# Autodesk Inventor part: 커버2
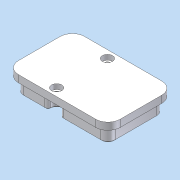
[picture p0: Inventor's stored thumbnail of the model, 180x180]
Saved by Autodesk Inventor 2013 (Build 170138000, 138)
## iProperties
Company: 한국ATC센터
Created: 2015-04
Part Number: 커버2
Document SubType Name: Modeling
Designer: KYOUNG IL JANG
Density: 1 g/cm^3
Material: 알루미늄 6061
Mass: 82.2849 g
Surface Area: 213.51 cm^2
Volume: 82.2849 cm^3
Author: KYOUNG IL JANG
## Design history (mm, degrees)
node "작업 평면1"
sketch "스케치1"
  geometry: L1 (-16.986, 27.5)-(-38, 27.5) reference; L2 (-45, 20.5)-(-45, -20.5) reference; L3 (-38, -27.5)-(-16.986, -27.5) reference; L4 (0.986, -27.5)-(38, -27.5) reference; L5 (45, -20.5)-(45, 20.5) reference; L6 (38, 27.5)-(0.986, 27.5) reference; C1 r 25 at (15, 0); A1 r 3 centre (-16.986, 24.5) between (-13.991, 24.667) and (-16.986, 27.5) reference; A2 r 7 centre (-38, 20.5) between (-38, 27.5) and (-45, 20.5) reference; A3 r 7 centre (-38, -20.5) between (-45, -20.5) and (-38, -27.5) reference; A4 r 3 centre (-16.986, -24.5) between (-16.986, -27.5) and (-13.991, -24.667) reference; A5 r 6 centre (-8, -25) between (-2.009, -24.667) and (-13.991, -24.667) reference; A6 r 3 centre (0.986, -24.5) between (-2.009, -24.667) and (0.986, -27.5) reference; A7 r 7 centre (38, -20.5) between (38, -27.5) and (45, -20.5) reference; A8 r 7 centre (38, 20.5) between (45, 20.5) and (38, 27.5) reference; A9 r 3 centre (0.986, 24.5) between (0.986, 27.5) and (-2.009, 24.667) reference; A10 r 6 centre (-8, 25) between (-13.991, 24.667) and (-2.009, 24.667) reference; 1 further point
  constraints: 20 point on circle, 12 end point, 11 centre point, 4 horizontal, 2 vertical, 36 other
extrude "돌출1" new body sketch "스케치1" distance "d0" = 14; taper "d1" = 0 deg
sketch "스케치2"
  geometry: L1 (38, -32.5)-(-38, -32.5) reference; L2 (50, 20.5)-(50, -20.5) reference; L3 (-38, 32.5)-(38, 32.5) reference; L4 (-50, -20.5)-(-50, 20.5) reference; A1 r 12 centre (38, -20.5) between (38, -32.5) and (50, -20.5) reference; A2 r 12 centre (38, 20.5) between (50, 20.5) and (38, 32.5) reference; A3 r 12 centre (-38, 20.5) between (-38, 32.5) and (-50, 20.5) reference; A4 r 12 centre (-38, -20.5) between (-50, -20.5) and (-38, -32.5) reference; 1 further point
extrude "돌출2" join sketch "스케치2" distance "d2" = 7; taper "d3" = 0 deg
sketch "스케치3"
  geometry: C1 r 2.458 at (-8, 25) reference; C2 r 2.458 at (-8, -25) reference; 1 further point
hole "구멍1" sketch "스케치3" at (-8, -25), (-8, 25) diameter "d4" = 6; stored, may be unused: countersink angle "d8" = 90 deg, drill point angle "d10" = 118 deg; dims "d5" = 6, "d6" = 10, "d7" = 5, "d9" = 8
fillet "모깎기1" dims "d11" = 0.3
chamfer "모따기1" distance "d12" = 1; stored, may be unused: second distance "d13" = 2, angle "d14" = 45 deg
node "솔리드1"
node "참조2"
node "참조3"
node "참조4"
node "참조5"
node "참조6"
node "참조7"
node "참조8"
node "참조9"
node "참조10"
node "참조11"
